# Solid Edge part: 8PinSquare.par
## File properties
Author: conerly
Template: ansi part.par
Last saved by: alogan
Revision: 21
Application: Solid Edge
Density: 0.03699434701 lbm/in^3
Accuracy: 0.990
Material: ABS Plastic, high impact
Face Style: Red
Fill Style: ANSI34(Plastic)
Virtual Style: Red (Shiny)
Coef. of Thermal Exp: 9e-05
Thermal Conductivity: 0.2
Specific Heat: 0.0
Modulus of Elasticity: 1378951400.0
Poisson's Ratio: 0.4
Yield Stress: 31026406.5
Ultimate Stress: 0.0
Elongation: 0.0
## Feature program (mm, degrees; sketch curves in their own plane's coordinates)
sketch for "unnamed Protrusion 1" plane through (0, 0, 0) normal (0, -1, 0) x-axis (1, 0, 0)
  line (-12.7, -6.35) -> (12.7, -6.35)
  line (12.7, -6.35) -> (12.7, 6.35)
  line (12.7, 6.35) -> (-12.7, 6.35)
  line (-12.7, 6.35) -> (-12.7, -6.35)
  dimension (linear) = 12.7
  dimension (linear) = 12.7
extrude "unnamed Protrusion 1" add finite 25.4 along -normal
sketch for "ExtrudedCutout_1" plane through (0, 0, 0) normal (0, -1, 0) x-axis (1, 0, 0)
  circle centre (-10.16, 3.81) radius 1.0489
extrude "ExtrudedCutout_1" cut finite 1.27 along -normal
pattern "unnamed Pattern 1" of "ExtrudedCutout_1"
extrude "unnamed Cutout 1" cut finite 1.27
extrude "unnamed Cutout 2" cut finite 1.27
extrude "unnamed Cutout 3" cut finite 1.27
extrude "unnamed Cutout 4" cut finite 1.27
extrude "unnamed Cutout 5" cut finite 1.27
extrude "unnamed Cutout 6" cut finite 1.27
extrude "unnamed Cutout 7" cut finite 1.27
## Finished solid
Body 1: solid body, 22 faces, 28 edges, 8 vertices.
  Faces by surface: plane 14, cylinder 8
  Edges by curve: circle 16, line 12
Bounding box of the edges (mm): 25.400 x 25.400 x 12.700, from (-12.7, 0, -6.35) to (12.7, 25.4, 6.35).
Cylindrical faces by radius (mm): R1.0489 x8
Planar faces by outward normal: +x 1, +y 1, +z 1, -x 1, -y 9, -z 1
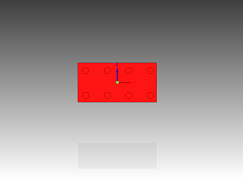
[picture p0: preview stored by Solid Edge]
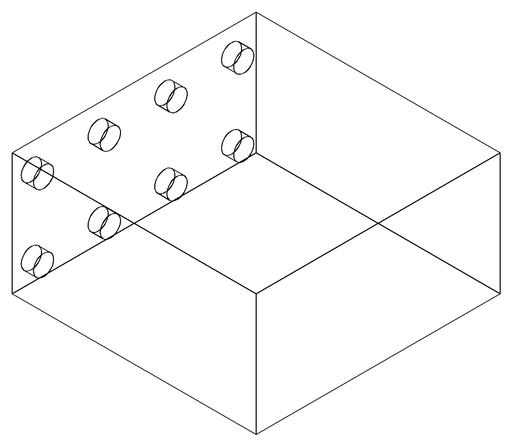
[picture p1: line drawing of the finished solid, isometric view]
